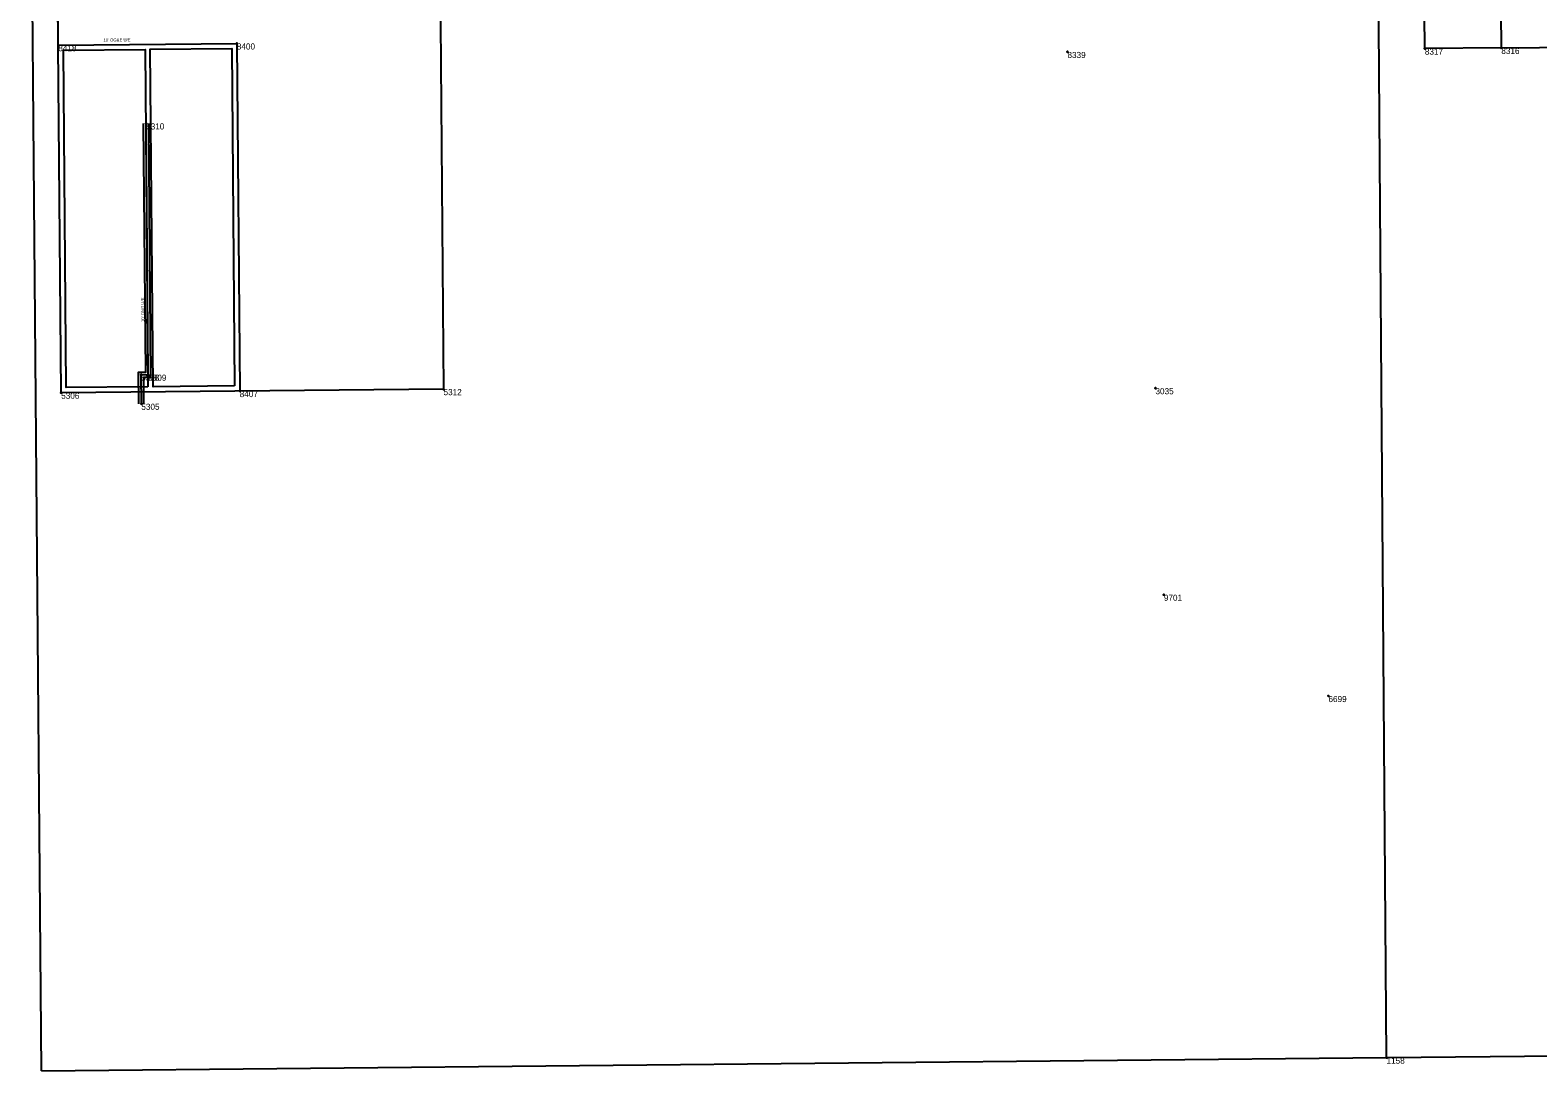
# Model space of a CAD drawing. Extents: x 2145146 to 2158053, y 137507 to 150829.
# Drawn here: x 2145642 to 2148600, y 140313 to 142349 of the extents above; entities that cross this region are included whole.
import ezdxf

# ---------------------------------------------------------------- set-up
doc = ezdxf.new("R2010")
doc.units = 0
for name, color, linetype in [('ALIGN_Cogo Points', 7, 'Continuous'), ('ALIGN_ROW Line', 7, 'Continuous'), ('PLSS_Easement', 7, 'Continuous'), ('PLSS_Property Line', 7, 'Continuous'), ('PLSS_Section Line', 7, 'Continuous'), ('PLSS_Text', 7, 'Continuous')]:
    doc.layers.add(name, color=color, linetype=linetype)

msp = doc.modelspace()

# ---------------------------------------------------------------- linework, layer by layer
at = {"layer": 'ALIGN_Cogo Points'}
for points in [[(2145697.5, 142320), (2145697.5, 142321.2), (2145697.5, 142320), (2145696.3, 142320), (2145697.5, 142320), (2145697.5, 142318.8), (2145697.5, 142320), (2145698.7, 142320)], [(2146047.7, 142323.3), (2146047.7, 142324.5), (2146047.7, 142323.3), (2146046.5, 142323.3), (2146047.7, 142323.3), (2146047.7, 142322.1), (2146047.7, 142323.3), (2146048.9, 142323.3)], [(2147677, 142306.6), (2147677, 142307.8), (2147677, 142306.6), (2147675.8, 142306.6), (2147677, 142306.6), (2147677, 142305.4), (2147677, 142306.6), (2147678.2, 142306.6)], [(2148378, 142313.2), (2148378, 142314.4), (2148378, 142313.2), (2148376.8, 142313.2), (2148378, 142313.2), (2148378, 142312), (2148378, 142313.2), (2148379.2, 142313.2)], [(2148528, 142314.6), (2148528, 142315.8), (2148528, 142314.6), (2148526.8, 142314.6), (2148528, 142314.6), (2148528, 142313.4), (2148528, 142314.6), (2148529.2, 142314.6)], [(2145869.8, 142166.4), (2145869.8, 142167.6), (2145869.8, 142166.4), (2145868.6, 142166.4), (2145869.8, 142166.4), (2145869.8, 142165.2), (2145869.8, 142166.4), (2145871, 142166.4)], [(2145859.9, 141673.3), (2145859.9, 141674.5), (2145859.9, 141673.3), (2145858.7, 141673.3), (2145859.9, 141673.3), (2145859.9, 141672.1), (2145859.9, 141673.3), (2145861.1, 141673.3)], [(2145873.9, 141673.4), (2145873.9, 141674.6), (2145873.9, 141673.4), (2145872.7, 141673.4), (2145873.9, 141673.4), (2145873.9, 141672.2), (2145873.9, 141673.4), (2145875.1, 141673.4)], [(2145703.2, 141638), (2145703.2, 141639.2), (2145703.2, 141638), (2145702, 141638), (2145703.2, 141638), (2145703.2, 141636.8), (2145703.2, 141638), (2145704.4, 141638)], [(2146053.3, 141641.3), (2146053.3, 141642.5), (2146053.3, 141641.3), (2146052.1, 141641.3), (2146053.3, 141641.3), (2146053.3, 141640.1), (2146053.3, 141641.3), (2146054.5, 141641.3)], [(2146453.2, 141645.1), (2146453.2, 141646.3), (2146453.2, 141645.1), (2146452, 141645.1), (2146453.2, 141645.1), (2146453.2, 141643.9), (2146453.2, 141645.1), (2146454.4, 141645.1)], [(2147849.6, 141646.9), (2147849.6, 141648.1), (2147849.6, 141646.9), (2147848.4, 141646.9), (2147849.6, 141646.9), (2147849.6, 141645.7), (2147849.6, 141646.9), (2147850.8, 141646.9)], [(2145860.4, 141616.3), (2145860.4, 141617.5), (2145860.4, 141616.3), (2145859.2, 141616.3), (2145860.4, 141616.3), (2145860.4, 141615.1), (2145860.4, 141616.3), (2145861.6, 141616.3)], [(2147866.1, 141241.6), (2147866.1, 141242.8), (2147866.1, 141241.6), (2147864.9, 141241.6), (2147866.1, 141241.6), (2147866.1, 141240.4), (2147866.1, 141241.6), (2147867.3, 141241.6)], [(2148188.9, 141042.9), (2148188.9, 141044.1), (2148188.9, 141042.9), (2148187.7, 141042.9), (2148188.9, 141042.9), (2148188.9, 141041.7), (2148188.9, 141042.9), (2148190.1, 141042.9)], [(2148302.8, 140333.3), (2148302.8, 140334.5), (2148302.8, 140333.3), (2148301.6, 140333.3), (2148302.8, 140333.3), (2148302.8, 140332.1), (2148302.8, 140333.3), (2148304, 140333.3)]]:
    msp.add_lwpolyline(points, dxfattribs=at)
at = {"layer": 'ALIGN_ROW Line'}
msp.add_lwpolyline([(2145697.5, 142320), (2145695.8, 142528), (2145694.4, 142695), (2145693.2, 142837.3), (2145742.7, 142890), (2145892.7, 142898.1), (2146317.5, 142920.9), (2146709.2, 142924.5), (2146892.6, 142919.5), (2147092.7, 142912.3), (2147276.6, 142905.6), (2147342.4, 142856.8), (2147438.8, 142564.4)], dxfattribs=at)
at = {"layer": 'PLSS_Easement'}
for points in [[(2145697.5, 142320), (2146047.7, 142323.3), (2146053.3, 141641.3)], [(2145873.1, 141649.6), (2145713.1, 141648.1), (2145707.6, 142310.1), (2145867.6, 142311.6), (2145873.1, 141649.6)], [(2146043.3, 141651.2), (2145883.3, 141649.7), (2145877.8, 142311.7), (2146037.8, 142313.2), (2146043.3, 141651.2)], [(2145855.4, 141616.2), (2145854.9, 141678.2), (2145868.9, 141678.3), (2145864.8, 142166.3)], [(2145860.4, 141616.3), (2145859.9, 141673.3), (2145873.9, 141673.4), (2145869.8, 142166.4)], [(2145865.4, 141616.3), (2145865, 141668.3), (2145879, 141668.4), (2145874.8, 142166.4)]]:
    msp.add_lwpolyline(points, dxfattribs=at)
at = {"layer": 'PLSS_Property Line'}
for points in [[(2148522.1, 142941.6), (2148528, 142314.6), (2148827.7, 142317.4)], [(2146442.6, 142922), (2146453.2, 141645.1), (2145703.2, 141638), (2145697.5, 142320), (2145694.5, 142680)], [(2148528, 142314.6), (2148378, 142313.2), (2148376.1, 142513.2), (2148226.2, 142511.8), (2148224.6, 142651.8), (2148223.9, 142748.8), (2148223.5, 142791.8), (2148136, 142790.9), (2148134.8, 142920.9)]]:
    msp.add_lwpolyline(points, dxfattribs=at)
at = {"layer": 'PLSS_Section Line'}
for points in [[(2148302.8, 140333.3), (2148283.1, 142972.3)], [(2145664.3, 140307.7), (2145642.3, 142947.5)], [(2148302.8, 140333.3), (2150945, 140358.9)], [(2145664.3, 140307.7), (2148302.8, 140333.3)]]:
    msp.add_lwpolyline(points, dxfattribs=at)

# ---------------------------------------------------------------- texts
at = {"layer": 'ALIGN_Cogo Points'}
for s, p in [('8418', (2145697.5, 142308)), ('8400', (2146047.7, 142311.3)), ('8339', (2147677, 142294.6)), ('8317', (2148378, 142301.2)), ('8316', (2148528, 142302.6)), ('5310', (2145869.8, 142154.4)), ('5308', (2145859.9, 141661.3)), ('5309', (2145873.9, 141661.4)), ('5306', (2145703.2, 141626)), ('8407', (2146053.3, 141629.3)), ('5312', (2146453.2, 141633.1)), ('3035', (2147849.6, 141634.9)), ('5305', (2145860.4, 141604.3)), ('9701', (2147866.1, 141229.6)), ('6699', (2148188.9, 141030.9)), ('1158', (2148302.8, 140321.3))]:
    msp.add_text(s, height=12, dxfattribs=at).set_placement(p)
at = {"layer": 'PLSS_Text'}
for s, rotation, p in [("10' OG&E U/E", 0.4679, (2145786.1, 142326.8)), ("10' ONG U/E", 90.4589, (2145866.3, 141776.6))]:
    msp.add_text(s, height=6, rotation=rotation, dxfattribs=at).set_placement(p)

doc.saveas('drawing.dxf')
